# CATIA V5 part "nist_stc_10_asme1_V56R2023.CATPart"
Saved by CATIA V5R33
Part number: nist_ftc_10_asme1
Nomenclature: nist_ftc_10_asme1
Source: Unknown
Bounding box of the stored display mesh (mm): x -78.989 to 78.989, y 0 to 31, z -37.5 to 37.5
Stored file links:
  C:\Users\rla3\OneDrive - NIST\STEP\NIST Test Models\STC\NIST_STC\10\V5\nist_stc_10_asme1_V56R2023_20231206.CATPart
  C:\Program Files\Dassault Systemes\B32\win_b64\resources\graphic\CATTPSGeneralTolerance.xlsx
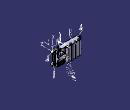
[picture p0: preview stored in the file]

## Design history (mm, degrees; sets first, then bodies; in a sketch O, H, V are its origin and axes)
TTRSSet1
f4a2d38f3ddc11d3a929006094b99c4b_11 "CATTPSSet"
Set1 "MBD_ABCDE"
  AxisSystem1 "ABC": origin (70, 0, 28.5), X (0, 0, 1), Y (-140, 0, 0), Z (0, -1, 0)
Set2 "MBD_B"
  AxisSystem2 "AJ": origin (47.5, 0, 37.5), X (1, 0, 0), Y (0, 1, 0), Z (0, 0, 1)
  Line1: stored without definition
  Line2: type PtDir, RefPoint {point type OnCurve, Support edge [face of Solid1 | face of Solid1], Ratio 0.5}, Direction face of Solid1, Start 15, End 27
  Extract1: ExtractElem face of Solid1
  Extract2: ExtractElem face of Solid1
  Join1: Elements (Extract2; Extract1), ElementsToFederate (face of Solid1; face of Solid1)
  Plane1: type Offset, RefPlane face of Solid1, Offset -2, reversed
  Split1: ToCut Join1, Cutting Plane1
  AxisLine1: Element face of Solid1
  Plane2: type Offset, RefPlane face of Solid1, Offset 0, reversed
  Intersect1: ToIntersect1 AxisLine1, ToIntersect2 Plane2
  AxisSystem3 "DE-F-G": origin (44.5, 27, -25), X (0, 0, -1), Y (-11, 0, 0), Z (0, 1, 0)
  AxisLine2: Element face of Solid1
  Plane3: type Offset, RefPlane face of Solid1, Offset 0, reversed
  Intersect2: ToIntersect1 AxisLine2, ToIntersect2 Plane3
  AxisSystem4 "H": origin (61.7906, 31, 23.5), X (-0.0379, 0, -0.9993), Y (-0.9993, 0, 0.0379), Z (0, 1, 0)
Set3 "MBD_C"
  Extract3: ExtractElem face of Solid1
  Extract4: ExtractElem face of Solid1
  Join2: Elements (Extract3; Extract4), ElementsToFederate (face of Solid1; face of Solid1)
  Split2: ToCut Join2, Cutting Plane1
  AxisSystem5 "DBC": origin (44.5, 27, -25), X (0, 0, -1), Y (-1, 0, 0), Z (0, 1, 0)
Set4 "MBD_D"
  Sketch1 on face of Solid1, origin (0, 31, 0), H (-1, 0, 0), V (0, 0, 1)
    reference projected arc E1 centre (-52, 23.5) radius 7.5 from (-52, 31) to (-52, 16) ccw from edge [face of Solid1 | face of Solid1]
    point P1 (-52, 31)
    point P2 (-52, 16)
    reference projected arc E2 centre (-43, 23.5) radius 7.5 from (-43, 16) to (-43, 31) ccw from edge [face of Solid1 | face of Solid1]
    point P3 (-43, 16)
    point P4 (-43, 31)
    point P5 (-52.0003, 23.5)
    line L1 (-61.7906, 23.5) -> (-55.4543, 31.0513)
    point P6 (-61.7906, 23.5)
    point P8 (-43, 23.5)
    construction line L2 (-62, 23.5) -> (-31, 23.5)
    line L3 (-61.7906, 23.5) -> (-55.4543, 15.9487)
    point P13 (-33.2094, 23.5)
    line L4 (-33.2094, 23.5) -> (-39.5459, 31.0515)
    line L5 (-33.2094, 23.5) -> (-39.5839, 15.9032)
    radius E1 = 7.5 (reference)
    distance P5 P1 = 7.5
    distance P5 P2 = 7.5
    distance P8 P4 = 7.5
    distance P8 P3 = 7.5
    distance L2 P8 = 0
    angle L1 L3 = 100
    angle L4 L5 = 100
    horizontal: L2 H
    coincidence: P6 L2, P13 L2
    tangency: E1 L1, L3 E1, E2 L4, L5 E2
  Extract5: ExtractElem face of Solid1
  Extract6: ExtractElem face of Solid1
  AxisSystem6 "DEB": origin (33.5, 27, -25), X (-0.0379, 0, -0.9993), Y (-0.9993, 0, 0.0379), Z (0, 1, 0)
  AxisSystem7 "DFB": origin (44.5, 27, -25), X (-0.0379, 0, -0.9993), Y (-0.9993, 0, 0.0379), Z (0, 1, 0)
  AxisSystem8 "DGB": origin (55.5, 27, -25), X (-0.0379, 0, -0.9993), Y (-0.9993, 0, 0.0379), Z (0, 1, 0)
Body1 "Solid1" (main body)
  Solid1: solid without history
  Thread1: "M3", diameter 3, depth 10, pitch 0.5, on face of Solid1, from face of Solid1
  Thread2: "M3", diameter 3, depth 10, pitch 0.5, on face of Solid1, from face of Solid1
  Thread3: "M3", diameter 3, depth 10, pitch 0.5, on face of Solid1, from face of Solid1
  Thread4: "M3", diameter 3, depth 10, pitch 0.5, on face of Solid1, from face of Solid1
  Thread5: "M3", diameter 3, depth 10, pitch 0.5, on face of Solid1, from face of Solid1
  Thread6: "M3", diameter 3, depth 10, pitch 0.5, on face of Solid1, from face of Solid1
